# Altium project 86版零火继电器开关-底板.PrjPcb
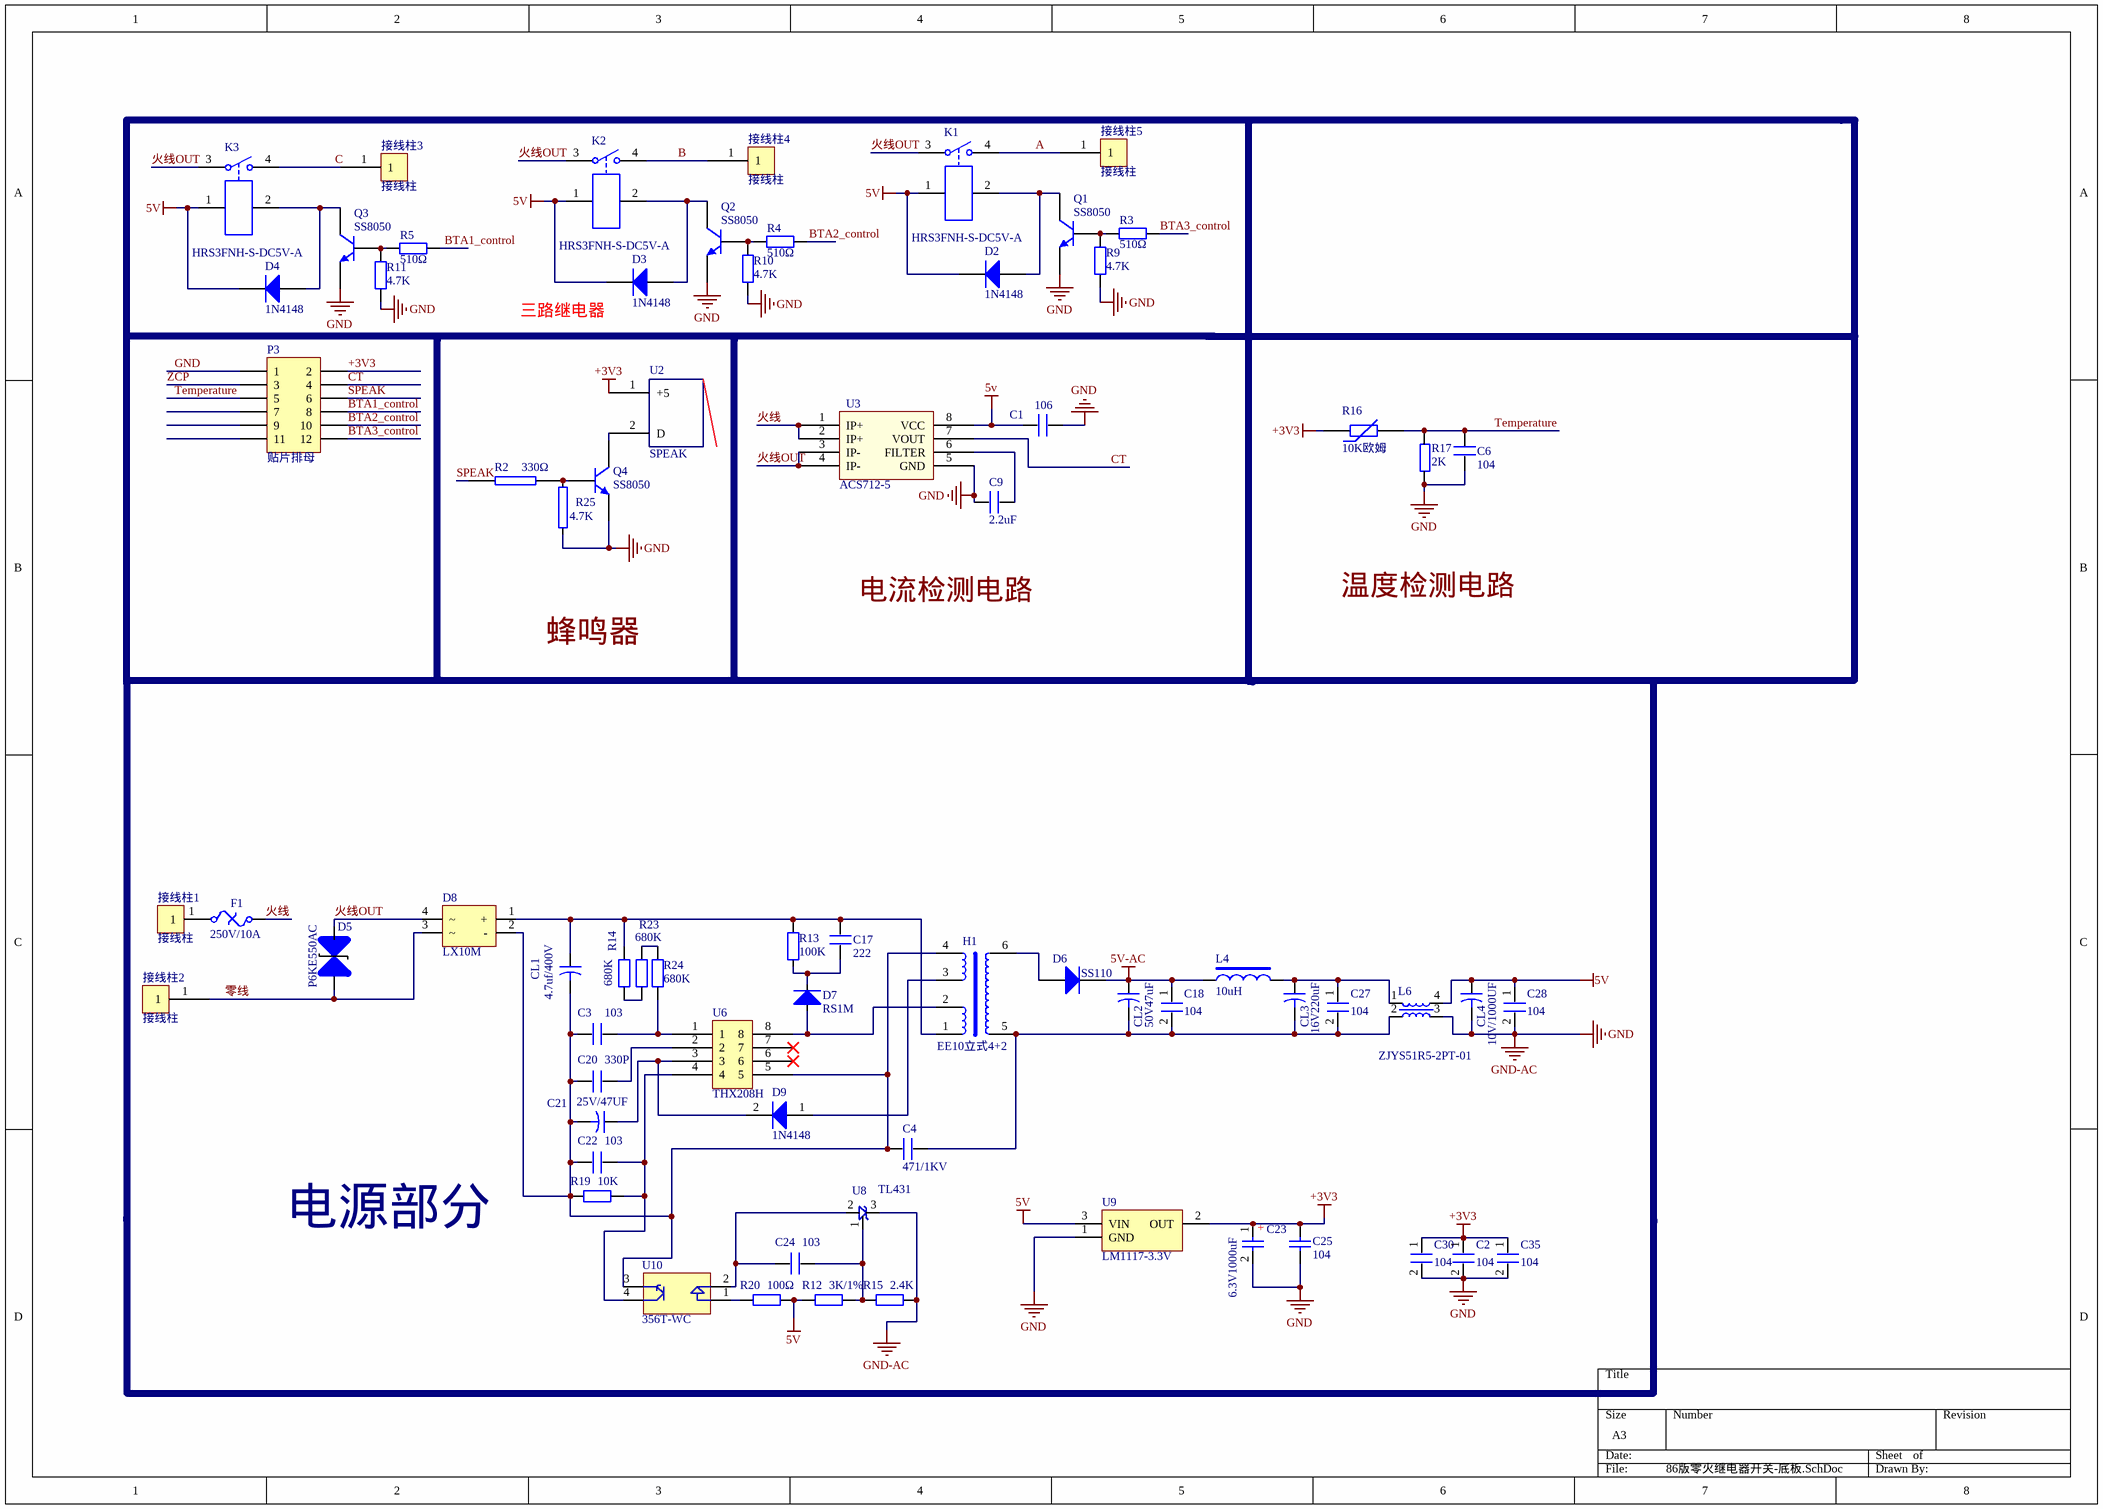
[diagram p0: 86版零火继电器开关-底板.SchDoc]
1 sheet, 71 parts. Net scope: global (net labels, ports and power ports of the same name join across sheets).
Board file: 86版零火继电器开关-底板.PcbDoc

## Sheet 86版零火继电器开关-底板.SchDoc
size A3

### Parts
C1  106  [0603P]
C2  104  [0603P]
C3  103  [0603p]
C4  471/1KV  [200mil]
C6  104  [0603P]
C9  2.2uF  [0603P]
C17  222  [200mil]
C18  104  [0603P]
C20  330P  [0603p]
C21  25V/47UF  [CAP5*2]
C22  103  [0603p]
C23  6.3V1000uF  [CAP8*10.2]
C24  103  [0603p]
C25  104  [0603P]
C27  104  [0603P]
C28  104  [0603P]
C30  104  [0603P]
C35  104  [0603P]
CL1  4.7uf/400V  [CAP8*12]
CL2  50V47uF  [CAP6.3*5.4]
CL3  16V220uF  [CAP6.3*5.4]
CL4  10V/1000UF  [CAP8*10.2]
D2  1N4148  [1206]
D3  1N4148  [1206]
D4  1N4148  [1206]
D5  P6KE550AC  [DO-15立式]
D6  SS110  [3.2X1.6X1.1]
D7  RS1M  [3.2X1.6X1.1]
D8  LX10M  [MBCN]
D9  1N4148  [1206]
F1  250V/10A  [2410]
H1  EE10立式4+2  [EE10-6]
K1  HRS3FNH-S-DC5V-A  [SJ-S-105]
K2  HRS3FNH-S-DC5V-A  [SJ-S-105]
K3  HRS3FNH-S-DC5V-A  [SJ-S-105]
L4  10uH  [CD32NP]
L6  ZJYS51R5-2PT-01  [SOP-4N]
P3  贴片排母  [贴片排母1.27MM2*6]
Q1  SS8050  [SOT23]
Q2  SS8050  [SOT23]
Q3  SS8050  [SOT23]
Q4  SS8050  [SOT23]
R2  330Ω  [0603P]
R3  510Ω  [0603P]
R4  510Ω  [0603P]
R5  510Ω  [0603P]
R9  4.7K  [0603P]
R10  4.7K  [0603P]
R11  4.7K  [0603P]
R12  3K/1%  [0603P]
R13  100K  [1206]
R14  680K  [0805]
R15  2.4K  [0603P]
R16  10K欧姆  [0603p]
R17  2K  [0603P]
R19  10K  [0603P]
R20  100Ω  [0603P]
R23  680K  [0805]
R24  680K  [0805]
R25  4.7K  [0603P]
U2  SPEAK  [Speak-9*5.5]
U3  ACS712-5  [SO8_L]
U6  THX208H  [SO8_L_6]
U8  TL431  [SOT23]
U9  LM1117-3.3V  [SOT89M]
U10  356T-WC  [SOP4 - EL357N]
接线柱1  接线柱  [5*6*10]
接线柱2  接线柱  [5*6*10]
接线柱3  接线柱  [5*6*10]
接线柱4  接线柱  [5*6*10]
接线柱5  接线柱  [5*6*10]

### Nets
5V: C1.1 C28.1 CL4.1 D2.2(K) D3.2(K) D4.2(K) K1.1 K2.1 K3.1 L6.4 R12.2 R20.1 U3.8(VCC) U9.3(VIN)
5V-AC: C18.1 CL2.1 D6.2(K) L4.1
+3V3: C2.1 C23.1 C25.2 C30.1 C35.1 P3.2 R16.1 U2.1(+5) U9.2(OUT)
GND: C1.2 C2.2 C6.1 C9.2 C23.2 C25.1 C28.2 C30.2 C35.2 CL4.2 L6.3 P3.1 Q1.2(E) Q2.2(E) Q3.2(E) Q4.2(E) R9.2 R10.2 R11.2 R15.1 R17.1 R25.2 U3.5(GND) U8.3 U9.1(GND)  [also labelled GND-AC]
A: K1.4 接线柱5.1
B: K2.4 接线柱4.1
BTA1_control: P3.8 R5.1
BTA2_control: P3.10 R4.1
BTA3_control: P3.12 R3.1
C: K3.4 接线柱3.1
CT: P3.4 U3.7(VOUT)
SPEAK: P3.6 R2.2
Temperature: C6.2 P3.5 R16.2 R17.2
ZCP: P3.3
火线: F1.1 U3.1(IP+) U3.2(IP+)
火线OUT: D5.2 D8.4 K1.3 K2.3 K3.3 U3.3(IP-) U3.4(IP-)
零线: D5.1 D8.3 接线柱2.1
NetC3_1: C3.1 R24.1 U6.1
NetC3_2: C3.2 C4.1 C20.2 C21.2 C22.2 CL1.2 D8.2(-) H1.4 R19.2 U6.5 U10.3(E)
NetC4_2: C4.2 C18.2 C27.2 CL2.2 CL3.2 H1.5 L6.2
NetC9_1: C9.1 U3.6(FILTER)
NetC17_1: C17.1 CL1.1 D8.1(+) H1.1 R13.1 R14.2
NetC17_2: C17.2 D7.2(K) R13.2
NetC20_1: C20.1 U6.2
NetC21_1: C21.1 D9.2(K) U6.3
NetC22_1: C22.1 R19.1 U6.4 U10.4(D)
NetC24_1: C24.1 R12.1 R15.2 U8.1
NetC24_2: C24.2 U8.2 U10.2
NetC27_1: C27.1 CL3.1 L4.2 L6.1
NetD2_1: D2.1(A) K1.2 Q1.3(C)
NetD3_1: D3.1(A) K2.2 Q2.3(C)
NetD4_1: D4.1(A) K3.2 Q3.3(C)
NetD6_1: D6.1(A) H1.6
NetD7_1: D7.1(A) H1.2 U6.8
NetD9_1: D9.1(A) H1.3
NetF1_2: F1.2 接线柱1.1
NetQ1_1: Q1.1(B) R3.2 R9.1
NetQ2_1: Q2.1(B) R4.2 R10.1
NetQ3_1: Q3.1(B) R5.2 R11.1
NetQ4_1: Q4.1(B) R2.1 R25.1
NetQ4_3: Q4.3(C) U2.2(D)
NetR14_1: R14.1 R23.1
NetR20_2: R20.2 U10.1
NetR23_2: R23.2 R24.2

Not connected (* = marked no-connect by the designer): P3 7 9 11; U6 6* 7*

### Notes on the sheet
- 三路继电器
- 电流检测电路
- 温度检测电路
- 电源部分
- Labels drawn without touching a wire or pin: 蜂鸣器

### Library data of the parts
C1-C3 C6 C9 C18 C20 C22 C24 C27 C28 C30 C35 = C: 贴片电容
C4 = C: 高压瓷片电容 471/1KV
C17 = C: 涤纶电容 222/1KV
C21 = Cap2: 直插电解电容 5*11; Value: 4.7uF/400V
C23 = CAP+: 贴片电解电容8*10.2
C25 = Cap: 贴片电容; Value: 0.1uF
CL1 = Cap2: 直插电解电容 8*12
CL2 CL3 = Cap2: 贴片电解电容 6.3*7.7; Value: 4.7uF/400V
CL4 = Cap2: 贴片电解电容 8*10.2; Value: 4.7uF/400V
D2-D4 D7 D9 = Diode: 贴片二极管
D5 = TVS: 直插式双向瞬抑制二极管
D6 = Diode: 贴片整流二极管
D8 = MB6S: 贴片整流桥
F1 = Fuse Thermal: 2410贴片保险丝
H1 = EE13立式4+4: 变压器
K1-K3 = Relay-SPST: 5V继电器
L4 = INDUCTOR2: CD32贴片电感
L6 = 共模电感: 贴片电感
P3 = Header 6X2: 贴片排母1.27MM2*6
Q1-Q3 = 2N3904: 贴片三极管
Q4 = SS8050: 贴片三极管
R2 R25 = RES2: 贴片电阻
R3-R5 R9-R11 R13 = Res2: 贴片电阻
R12 R14 R15 R19 R20 R23 R24 = Res2: 贴片电阻; Value: 100k
R16 = Res Varistor: 贴片温敏电阻,负温度系数 3950
R17 = R: 贴片电阻
U2 = SPEAK: 3.3V有源蜂鸣器，9*5.5
U3 = Component_1: 贴片电流检测芯片，5A，不焊接不用料
U6 = CON8: 贴片电源管理芯片
U8 = TL431: 贴片IC
U9 = LM1117: 贴片IC
U10 = NEC2701: 贴片光耦，C档
接线柱1-接线柱5 = 接线柱: 接线铜柱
